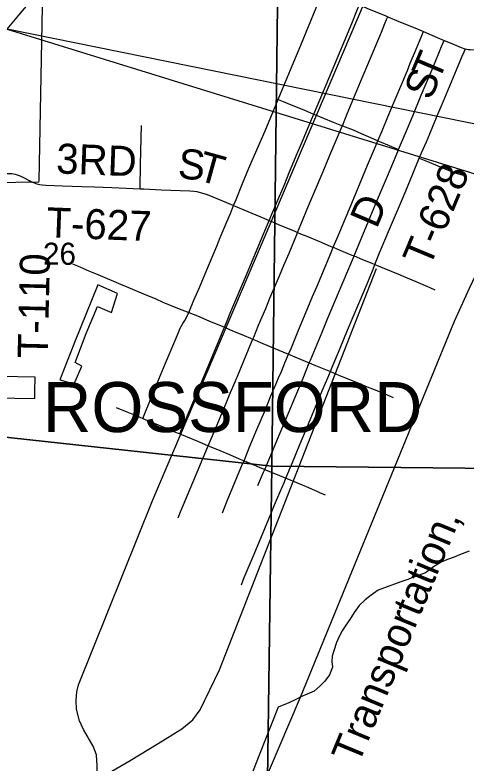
# Model space of a CAD drawing. Extents: x 0 to 34, y 0 to 22.
# Drawn here: x 7.043 to 7.896, y 18.272 to 19.688 of the extents above; entities that cross this region are included whole.
import ezdxf

# ---------------------------------------------------------------- set-up
doc = ezdxf.new("R2010")
doc.units = 0
for name, color, linetype in [('GM_X_Corporation', 7, 'Continuous'), ('GM_X_Corporation_Text', 7, 'Continuous'), ('GM_X_Interstate_Route', 7, 'Continuous'), ('GM_X_Minor_Lake', 7, 'Continuous'), ('GM_X_Minor_River', 7, 'Continuous'), ('GM_X_Rail_Line', 7, 'Continuous'), ('GM_X_Rail_Line_Text', 7, 'Continuous'), ('GM_X_Section_Text', 7, 'Continuous'), ('GM_X_Township_Road', 7, 'Continuous'), ('GM_X_Township_Road_Text', 7, 'Continuous'), ('SH_Text', 7, 'Continuous')]:
    doc.layers.add(name, color=color, linetype=linetype)

msp = doc.modelspace()

# ---------------------------------------------------------------- linework, layer by layer
at = {"layer": 'GM_X_Corporation'}
for points in [[(7.0187, 19.8969), (7.5413, 19.8609), (7.5285, 18.8343), (7.0065, 18.8908), (6.5045, 18.8781), (6.5124, 19.9044)], [(7.5413, 19.8609), (8.5695, 19.8537), (8.5696, 19.4474), (8.5646, 18.8232), (7.5285, 18.8343)], [(6.5045, 18.8781), (7.0065, 18.8908), (7.5285, 18.8343), (7.515, 17.8763), (6.497, 17.8754)], [(7.5285, 18.8343), (8.5646, 18.8232), (8.5626, 18.4264), (8.5579, 17.8652), (7.515, 17.8763)]]:
    msp.add_lwpolyline(points, close=True, dxfattribs=at)
for points in [[(7.0136, 19.3711), (7.0443, 19.3716), (7.0681, 19.3722), (7.0731, 19.3721), (7.0879, 19.3717), (7.0884, 19.3742), (7.0948, 19.704), (7.1392, 19.7592), (7.2066, 19.863), (7.2072, 19.878), (7.1312, 19.88), (7.0995, 19.8256), (7.0998, 19.8709), (7.026, 19.8729)], [(7.0043, 18.9635), (7.0803, 18.9624), (7.0806, 18.9763), (7.0811, 19.0029), (7.0142, 19.004)]]:
    msp.add_lwpolyline(points, dxfattribs=at)
at = {"layer": 'GM_X_Interstate_Route'}
msp.add_lwpolyline([(7.0065, 19.6356), (7.0182, 19.6495), (7.0279, 19.6612), (7.0503, 19.6879), (7.0677, 19.7089), (7.0821, 19.7268), (7.0969, 19.7463)], dxfattribs=at)
at = {"layer": 'GM_X_Minor_Lake'}
msp.add_line((7.1549, 18.9899), (7.169, 19.0235), dxfattribs=at)
msp.add_lwpolyline([(7.169, 19.0235), (7.1566, 19.0301), (7.1777, 19.0853), (7.1991, 19.1362), (7.2251, 19.1253), (7.2365, 19.1612), (7.1997, 19.1772), (7.1556, 19.0685), (7.1275, 18.9978), (7.1549, 18.9899)], dxfattribs=at)
at = {"layer": 'GM_X_Minor_River'}
for points in [[(7.9018, 18.6731), (7.8836, 18.6661), (7.873, 18.6617), (7.8608, 18.6573), (7.849, 18.6525), (7.8342, 18.6436), (7.8193, 18.632), (7.795, 18.6232), (7.7836, 18.6192), (7.7722, 18.6151), (7.7624, 18.6115), (7.7514, 18.6074), (7.7415, 18.6041), (7.7297, 18.5997), (7.7164, 18.5897), (7.7053, 18.5814), (7.6935, 18.5702), (7.6842, 18.557), (7.6757, 18.5439), (7.6684, 18.5329), (7.6615, 18.5224), (7.6561, 18.5118), (7.651, 18.5001), (7.6455, 18.4846), (7.6424, 18.4744), (7.6418, 18.4642), (7.6432, 18.4535), (7.6377, 18.4392), (7.6289, 18.4272), (7.6193, 18.4178), (7.6083, 18.4081), (7.5953, 18.4025), (7.5836, 18.3974), (7.5737, 18.3922), (7.5604, 18.3859), (7.5405, 18.3781)], [(7.5405, 18.3781), (7.5043, 18.2868), (7.4715, 18.2033), (7.438, 18.124), (7.3754, 18.0192)]]:
    msp.add_lwpolyline(points, dxfattribs=at)
at = {"layer": 'GM_X_Rail_Line'}
for points in [[(7.1918, 18.2168), (7.1976, 18.2415), (7.1985, 18.2668), (7.1971, 18.288), (7.1907, 18.3043), (7.1721, 18.3357), (7.1648, 18.3522), (7.1593, 18.374), (7.1584, 18.3906), (7.1596, 18.4069), (7.163, 18.42), (7.1898, 18.4877), (7.3035, 18.7703), (7.7161, 19.7423), (7.7367, 19.7856), (7.7522, 19.8033), (7.7707, 19.8183), (7.7881, 19.8278), (7.8054, 19.8353), (7.8226, 19.8392), (7.8515, 19.8421), (7.8923, 19.8423), (7.9335, 19.8404), (7.9913, 19.8421)], [(5.7724, 14.1), (5.9023, 14.4065), (6.108, 14.9012), (7.0925, 17.2371), (7.3462, 17.8422), (7.5826, 18.397), (7.8741, 19.1084), (7.9022, 19.1708), (7.9338, 19.2375), (7.9584, 19.2815), (7.9927, 19.3184), (8.0524, 19.3602), (8.3458, 19.5368)], [(7.1918, 18.2168), (7.209, 18.2434), (7.226, 18.2569), (7.2608, 18.2771), (7.3135, 18.309), (7.3583, 18.3368), (7.3791, 18.3538), (7.3932, 18.373), (7.4293, 18.4484), (7.7262, 19.2086)]]:
    msp.add_lwpolyline(points, dxfattribs=at)
at = {"layer": 'GM_X_Township_Road'}
msp.add_line((7.6078, 19.5006), (7.6178, 19.5243), dxfattribs=at)
for points in [[(7.5404, 19.5283), (7.5449, 19.539), (7.564, 19.5842), (7.5835, 19.6313), (7.6124, 19.7015), (7.6173, 19.7137), (7.6214, 19.7228), (7.6235, 19.7267), (7.6243, 19.7277), (7.6251, 19.7287), (7.626, 19.7294), (7.6271, 19.7302), (7.6285, 19.7308)], [(7.6178, 19.5243), (7.6411, 19.5799), (7.6796, 19.6723), (7.6907, 19.6993), (7.694, 19.7073)], [(7.694, 19.7073), (7.7082, 19.7014), (7.7441, 19.6864), (7.7479, 19.6848)], [(7.6619, 19.4784), (7.671, 19.5012), (7.6959, 19.5615), (7.7358, 19.656), (7.7425, 19.6722), (7.7455, 19.6794), (7.7479, 19.6848)], [(7.7479, 19.6848), (7.7687, 19.6761), (7.7956, 19.6649), (7.8151, 19.6567)], [(7.7291, 19.45), (7.7371, 19.4691), (7.748, 19.4955), (7.7615, 19.5283), (7.7849, 19.5832), (7.7904, 19.597), (7.8003, 19.6205), (7.8121, 19.6493), (7.8151, 19.6567)], [(7.8151, 19.6567), (7.8412, 19.6458), (7.8546, 19.6401)], [(7.7683, 19.4336), (7.7849, 19.4735), (7.795, 19.4976), (7.8111, 19.5367), (7.8334, 19.5893), (7.8496, 19.6284), (7.8521, 19.6341), (7.8546, 19.6401)], [(7.8546, 19.6401), (7.8596, 19.638), (7.873, 19.6324), (7.8868, 19.6267), (7.8937, 19.6243), (7.8947, 19.624)], [(7.8073, 19.417), (7.8115, 19.427), (7.8207, 19.4481), (7.8271, 19.463), (7.8409, 19.497), (7.8523, 19.5239), (7.8775, 19.5841), (7.8886, 19.6105), (7.8921, 19.6184), (7.8947, 19.624)], [(7.8947, 19.624), (7.8972, 19.6234), (7.8996, 19.623), (7.9033, 19.6229), (7.9329, 19.6224), (7.9573, 19.622), (7.9865, 19.6215), (8.0217, 19.6213), (8.0294, 19.6209), (8.0339, 19.6206), (8.0487, 19.6194)], [(7.456, 19.3275), (7.4608, 19.3391), (7.4732, 19.3692), (7.4851, 19.3982), (7.4999, 19.4331), (7.5156, 19.469), (7.5263, 19.4947), (7.5404, 19.5283)], [(7.5404, 19.5283), (7.5497, 19.5245), (7.5652, 19.5182), (7.5888, 19.5085), (7.6015, 19.5033), (7.6078, 19.5006)], [(7.5236, 19.2991), (7.5375, 19.3321), (7.5528, 19.3689), (7.5609, 19.3884), (7.5748, 19.4216), (7.5862, 19.4492), (7.6036, 19.4905), (7.6078, 19.5006)], [(7.6078, 19.5006), (7.6445, 19.4852), (7.6572, 19.4802), (7.6619, 19.4784)], [(7.2796, 19.3592), (7.2796, 19.364), (7.2797, 19.3696), (7.2802, 19.3957), (7.2803, 19.4044), (7.2813, 19.4555), (7.2823, 19.4791)], [(7.5773, 19.2767), (7.5834, 19.2918), (7.598, 19.3268), (7.6095, 19.3537), (7.6255, 19.3921), (7.6381, 19.4226), (7.6615, 19.4775), (7.6619, 19.4784)], [(7.6619, 19.4784), (7.6822, 19.4705), (7.6977, 19.4641), (7.7154, 19.4562), (7.7291, 19.45)], [(7.6446, 19.2484), (7.6518, 19.2656), (7.6751, 19.3212), (7.6915, 19.3608), (7.7095, 19.4038), (7.7226, 19.4347), (7.7291, 19.45)], [(7.7291, 19.45), (7.7318, 19.4488), (7.7507, 19.4409), (7.7639, 19.4354), (7.7683, 19.4336)], [(7.6841, 19.232), (7.6977, 19.2647), (7.7285, 19.3388), (7.7471, 19.3829), (7.7668, 19.4299), (7.7683, 19.4336)], [(7.7234, 19.2159), (7.7323, 19.2378), (7.7493, 19.2785), (7.7586, 19.3002), (7.7774, 19.3449), (7.795, 19.3874), (7.8073, 19.417)], [(7.8073, 19.417), (7.826, 19.4094), (7.8588, 19.396), (7.8668, 19.3927), (7.8726, 19.3906), (7.8755, 19.3896), (7.8793, 19.3884), (7.8908, 19.3849), (7.8944, 19.3839), (7.8968, 19.3833)], [(7.0239, 19.3884), (7.0287, 19.3884), (7.0366, 19.3879), (7.0429, 19.3867), (7.0487, 19.3849), (7.0539, 19.3829), (7.0589, 19.3806), (7.0698, 19.3747), (7.0749, 19.3722), (7.0789, 19.3706)], [(7.0789, 19.3706), (7.0844, 19.3687), (7.0893, 19.3675), (7.0942, 19.3667), (7.1011, 19.366), (7.1328, 19.3649), (7.1689, 19.3636), (7.1931, 19.3629), (7.2261, 19.3617), (7.2796, 19.3592)], [(7.2796, 19.3592), (7.2863, 19.3589), (7.3192, 19.3575), (7.3733, 19.3551), (7.3807, 19.3546), (7.3868, 19.3538), (7.3928, 19.3525), (7.3999, 19.3505), (7.4063, 19.3482), (7.435, 19.3363), (7.4545, 19.3281), (7.456, 19.3275)], [(7.3716, 19.1252), (7.3812, 19.1484), (7.3915, 19.1724), (7.4085, 19.2132), (7.4242, 19.2504), (7.431, 19.2671), (7.4315, 19.2683), (7.4433, 19.2964), (7.4502, 19.3124), (7.454, 19.3223), (7.456, 19.3275)], [(7.456, 19.3275), (7.4832, 19.3161), (7.5055, 19.3067), (7.5236, 19.2991)], [(7.4391, 19.097), (7.4427, 19.1058), (7.4512, 19.127), (7.4805, 19.1963), (7.504, 19.2525), (7.5236, 19.2991)], [(7.5236, 19.2991), (7.5308, 19.2961), (7.5468, 19.2893), (7.5709, 19.2794), (7.5773, 19.2767)], [(7.4926, 19.0745), (7.4942, 19.0784), (7.5036, 19.1008), (7.517, 19.1329), (7.525, 19.1519), (7.5429, 19.1942), (7.552, 19.216), (7.561, 19.2372), (7.5757, 19.2728), (7.5773, 19.2767)], [(7.5773, 19.2767), (7.5829, 19.2742), (7.5944, 19.2695), (7.622, 19.258), (7.6403, 19.2502), (7.6446, 19.2484)], [(7.5603, 19.0462), (7.5648, 19.0567), (7.5791, 19.0919), (7.5966, 19.1337), (7.6056, 19.1555), (7.6134, 19.1738), (7.6405, 19.2386), (7.6446, 19.2484)], [(7.6446, 19.2484), (7.6558, 19.2438), (7.6799, 19.2338), (7.6841, 19.232)], [(7.5994, 19.0299), (7.6014, 19.0348), (7.6238, 19.0881), (7.634, 19.1128), (7.6633, 19.1828), (7.6829, 19.2291), (7.6841, 19.232)], [(7.6841, 19.232), (7.7, 19.2254), (7.7173, 19.2184), (7.7234, 19.2159)], [(7.1517, 19.2171), (7.1609, 19.2131), (7.1836, 19.2034), (7.1995, 19.1967), (7.2426, 19.1787), (7.2528, 19.1741), (7.2861, 19.1604), (7.3089, 19.1506), (7.3226, 19.1447), (7.3501, 19.1334), (7.3716, 19.1252)], [(7.6393, 19.0131), (7.6427, 19.0218), (7.6579, 19.0573), (7.6716, 19.0913), (7.6825, 19.1171), (7.6928, 19.1418), (7.7086, 19.179), (7.72, 19.2072), (7.7234, 19.2159)], [(7.7234, 19.2159), (7.7679, 19.1973), (7.7811, 19.1917), (7.801, 19.1834), (7.8272, 19.1722), (7.8369, 19.168)], [(7.2846, 18.9246), (7.2871, 18.9306), (7.2978, 18.9571), (7.3059, 18.9767), (7.3148, 18.9986), (7.3277, 19.0289), (7.3517, 19.087), (7.3547, 19.0939), (7.3578, 19.1001), (7.3602, 19.1044), (7.3639, 19.1102), (7.3672, 19.1155), (7.3716, 19.1252)], [(7.3716, 19.1252), (7.3879, 19.1185), (7.4096, 19.1092), (7.4391, 19.097)], [(7.3545, 18.8953), (7.3566, 18.9004), (7.3792, 18.9543), (7.401, 19.0065), (7.4111, 19.0306), (7.4199, 19.0518), (7.43, 19.0759), (7.4391, 19.097)], [(7.4391, 19.097), (7.4543, 19.0904), (7.4716, 19.0833), (7.4926, 19.0745)], [(7.4083, 18.8728), (7.4211, 18.9034), (7.428, 18.9197), (7.4321, 18.9292), (7.4382, 18.9439), (7.45, 18.9723), (7.4591, 18.9936), (7.4612, 18.9987), (7.4627, 19.0026), (7.4698, 19.0199), (7.4902, 19.0686), (7.4926, 19.0745)], [(7.4926, 19.0745), (7.5117, 19.0665), (7.5341, 19.0572), (7.5496, 19.0507), (7.5603, 19.0462)], [(7.4759, 18.8445), (7.4859, 18.8687), (7.4984, 18.8992), (7.5163, 18.9416), (7.5269, 18.9675), (7.536, 18.9886), (7.5414, 19.0011), (7.5466, 19.0131), (7.5534, 19.0298), (7.5603, 19.0462)], [(7.5603, 19.0462), (7.584, 19.0362), (7.5994, 19.0299)], [(7.5151, 18.8279), (7.5441, 18.8971), (7.5875, 19.0009), (7.5994, 19.0299)], [(7.5994, 19.0299), (7.6081, 19.0262), (7.6299, 19.017), (7.6333, 19.0156), (7.6393, 19.0131)], [(7.5551, 18.8113), (7.5673, 18.8411), (7.5816, 18.8749), (7.5935, 18.9036), (7.6145, 18.9541), (7.6258, 18.9811), (7.6343, 19.0012), (7.6393, 19.0131)], [(7.6393, 19.0131), (7.6567, 19.0057), (7.6897, 18.9923), (7.7085, 18.9846), (7.7269, 18.9772), (7.7408, 18.9714), (7.7579, 18.9644)], [(7.2344, 18.9454), (7.2545, 18.937), (7.2735, 18.9292), (7.2846, 18.9246)], [(7.2846, 18.9246), (7.2889, 18.9228), (7.3273, 18.9065), (7.3399, 18.9012), (7.3497, 18.8973), (7.3545, 18.8953)], [(7.3545, 18.8953), (7.3652, 18.8909), (7.3899, 18.8807), (7.4083, 18.8728)], [(7.3513, 18.7365), (7.3559, 18.7474), (7.371, 18.7835), (7.3873, 18.8226), (7.4069, 18.8696), (7.4083, 18.8728)], [(7.4083, 18.8728), (7.4133, 18.8706), (7.4299, 18.8636), (7.4483, 18.856), (7.467, 18.8482), (7.4759, 18.8445)], [(7.435, 18.7459), (7.444, 18.7684), (7.4733, 18.8383), (7.4759, 18.8445)], [(7.4759, 18.8445), (7.4903, 18.8384), (7.5047, 18.8323), (7.5151, 18.8279)], [(7.5021, 18.7974), (7.5128, 18.8226), (7.5151, 18.8279)], [(7.5151, 18.8279), (7.5176, 18.8267), (7.5383, 18.8183), (7.5551, 18.8113)], [(7.4709, 18.6098), (7.4764, 18.6231), (7.4837, 18.6408), (7.4911, 18.6586), (7.4982, 18.6752), (7.5154, 18.7159), (7.5258, 18.7419), (7.5338, 18.7607), (7.5435, 18.7843), (7.5522, 18.8043), (7.5551, 18.8113)], [(7.5551, 18.8113), (7.5567, 18.8107), (7.5749, 18.8032), (7.586, 18.7986), (7.598, 18.7936), (7.6047, 18.7907), (7.6136, 18.7869), (7.6189, 18.7846), (7.6293, 18.7801)]]:
    msp.add_lwpolyline(points, dxfattribs=at)
at = {"layer": 'SH_Text'}
msp.add_lwpolyline([(7.0279, 19.6612), (9.327, 18.9498), (9.327, 19.1946)], close=True, dxfattribs=at)

# ---------------------------------------------------------------- texts
at = {"layer": 'GM_X_Corporation_Text'}
msp.add_text('ROSSFORD', height=0.0947, rotation=0, dxfattribs=at).set_placement((7.0957, 18.8987))
at = {"layer": 'GM_X_Rail_Line_Text'}
msp.add_text('Transportation,', height=0.056629, rotation=67.5274, dxfattribs=at).set_placement((7.6921, 18.2673))
at = {"layer": 'GM_X_Section_Text'}
msp.add_text('26', height=0.04186, rotation=0, dxfattribs=at).set_placement((7.0958, 19.2153))
at = {"layer": 'GM_X_Township_Road_Text'}
for s, height, rotation, p in [('T', 0.0568, 67.0676, (7.8437, 19.56)), ('S', 0.0568, 67.8209, (7.8293, 19.5247)), ('3RD', 0.05682, 357.8285, (7.12, 19.3884)), ('S', 0.0568, 354.9953, (7.3495, 19.3792)), ('T', 0.0568, 344.5032, (7.385, 19.3764)), ('T-628', 0.05682, 67.2738, (7.8267, 19.2079)), ('D', 0.0568, 66.9755, (7.7267, 19.282)), ('T-627', 0.05682, 357.7994, (7.1015, 19.2675)), ('T-110', 0.05682, 88.6032, (7.1044, 19.038))]:
    msp.add_text(s, height=height, rotation=rotation, dxfattribs=at).set_placement(p)

doc.saveas('drawing.dxf')
